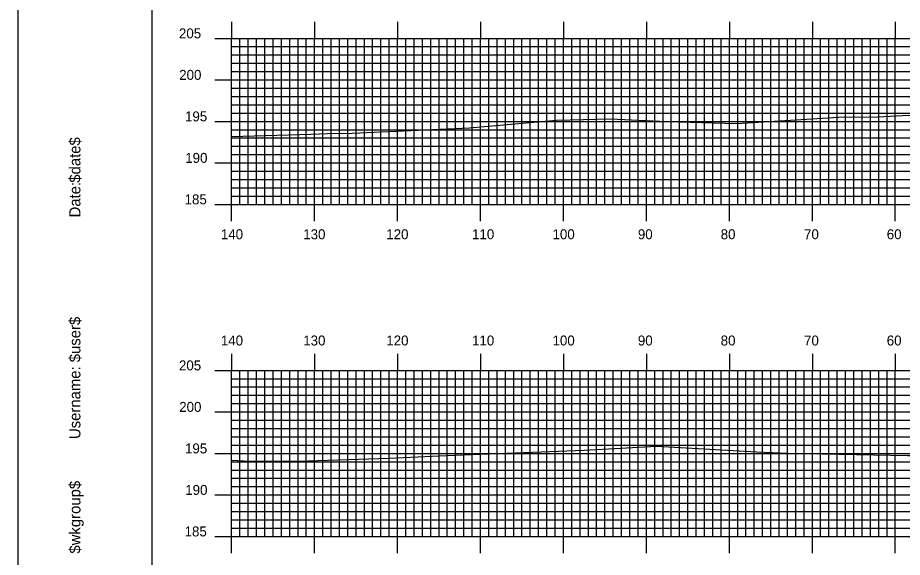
# Model space of a CAD drawing. Extents: x 1814522 to 1814865, y 442591 to 442811.
# Drawn here: x 1814521.7 to 1814628.4, y 442686.2 to 442751.2 of the extents above; entities that cross this region are included whole.
import ezdxf

# ---------------------------------------------------------------- set-up
doc = ezdxf.new("R2010")
doc.units = 0
for name, color, linetype in [('BORDER', 7, 'Continuous'), ('H_V ANNOTATION', 7, 'Continuous'), ('MAJOR', 7, 'Continuous'), ('MINOR', 7, 'Continuous'), ('PLOT BOUNDARY', 7, 'Continuous'), ('S_Roadway_Centerline', 7, 'Continuous')]:
    doc.layers.add(name, color=color, linetype=linetype)

msp = doc.modelspace()

# ---------------------------------------------------------------- linework, layer by layer
at = {"layer": 'BORDER'}
msp.add_lwpolyline([(1814537.91, 442596.67), (1814857.91, 442596.67), (1814857.91, 442806.67), (1814537.91, 442806.67)], close=True, dxfattribs=at)
at = {"layer": 'MAJOR'}
for p, q in [((1814547.51, 442750.67), (1814547.51, 442748.67)), ((1814557.51, 442750.67), (1814557.51, 442748.67)), ((1814567.51, 442750.67), (1814567.51, 442748.67)), ((1814577.51, 442750.67), (1814577.51, 442748.67)), ((1814587.51, 442750.67), (1814587.51, 442748.67)), ((1814597.51, 442750.67), (1814597.51, 442748.67)), ((1814607.51, 442750.67), (1814607.51, 442748.67)), ((1814617.51, 442750.67), (1814617.51, 442748.67)), ((1814627.51, 442750.67), (1814627.51, 442748.67)), ((1814545.5, 442748.67), (1814547.51, 442748.67)), ((1814547.51, 442748.67), (1814827.51, 442748.67)), ((1814547.51, 442728.67), (1814547.51, 442748.67)), ((1814547.51, 442728.67), (1814547.51, 442748.67)), ((1814547.51, 442748.67), (1814827.51, 442748.67)), ((1814557.51, 442728.67), (1814557.51, 442748.67)), ((1814567.51, 442728.67), (1814567.51, 442748.67)), ((1814577.51, 442728.67), (1814577.51, 442748.67)), ((1814587.51, 442728.67), (1814587.51, 442748.67)), ((1814597.51, 442728.67), (1814597.51, 442748.67)), ((1814607.51, 442728.67), (1814607.51, 442748.67)), ((1814617.51, 442728.67), (1814617.51, 442748.67)), ((1814627.51, 442728.67), (1814627.51, 442748.67)), ((1814545.5, 442743.67), (1814547.51, 442743.67)), ((1814547.51, 442743.67), (1814827.51, 442743.67)), ((1814545.5, 442738.67), (1814547.51, 442738.67)), ((1814547.51, 442738.67), (1814827.51, 442738.67)), ((1814545.5, 442733.67), (1814547.51, 442733.67)), ((1814547.51, 442733.67), (1814827.51, 442733.67)), ((1814545.5, 442728.67), (1814547.51, 442728.67)), ((1814547.51, 442728.67), (1814827.51, 442728.67)), ((1814547.51, 442728.67), (1814827.51, 442728.67)), ((1814547.51, 442726.66), (1814547.51, 442728.67)), ((1814557.51, 442726.66), (1814557.51, 442728.67)), ((1814567.51, 442726.66), (1814567.51, 442728.67)), ((1814577.51, 442726.66), (1814577.51, 442728.67)), ((1814587.51, 442726.66), (1814587.51, 442728.67)), ((1814597.51, 442726.66), (1814597.51, 442728.67)), ((1814607.51, 442726.66), (1814607.51, 442728.67)), ((1814617.51, 442726.66), (1814617.51, 442728.67)), ((1814627.51, 442726.66), (1814627.51, 442728.67)), ((1814547.51, 442710.67), (1814547.51, 442708.67)), ((1814557.51, 442710.67), (1814557.51, 442708.67)), ((1814567.51, 442710.67), (1814567.51, 442708.67)), ((1814577.51, 442710.67), (1814577.51, 442708.67)), ((1814587.51, 442710.67), (1814587.51, 442708.67)), ((1814597.51, 442710.67), (1814597.51, 442708.67)), ((1814607.51, 442710.67), (1814607.51, 442708.67)), ((1814617.51, 442710.67), (1814617.51, 442708.67)), ((1814627.51, 442710.67), (1814627.51, 442708.67)), ((1814545.5, 442708.67), (1814547.51, 442708.67)), ((1814547.51, 442708.67), (1814827.51, 442708.67)), ((1814547.51, 442688.67), (1814547.51, 442708.67)), ((1814547.51, 442688.67), (1814547.51, 442708.67)), ((1814547.51, 442708.67), (1814827.51, 442708.67)), ((1814557.51, 442688.67), (1814557.51, 442708.67)), ((1814567.51, 442688.67), (1814567.51, 442708.67)), ((1814577.51, 442688.67), (1814577.51, 442708.67)), ((1814587.51, 442688.67), (1814587.51, 442708.67)), ((1814597.51, 442688.67), (1814597.51, 442708.67)), ((1814607.51, 442688.67), (1814607.51, 442708.67)), ((1814617.51, 442688.67), (1814617.51, 442708.67)), ((1814627.51, 442688.67), (1814627.51, 442708.67)), ((1814545.5, 442703.67), (1814547.51, 442703.67)), ((1814547.51, 442703.67), (1814827.51, 442703.67)), ((1814545.5, 442698.67), (1814547.51, 442698.67)), ((1814547.51, 442698.67), (1814827.51, 442698.67)), ((1814545.5, 442693.67), (1814547.51, 442693.67)), ((1814547.51, 442693.67), (1814827.51, 442693.67)), ((1814545.5, 442688.67), (1814547.51, 442688.67)), ((1814547.51, 442688.67), (1814827.51, 442688.67)), ((1814547.51, 442688.67), (1814827.51, 442688.67)), ((1814547.51, 442686.66), (1814547.51, 442688.67)), ((1814557.51, 442686.66), (1814557.51, 442688.67)), ((1814567.51, 442686.66), (1814567.51, 442688.67)), ((1814577.51, 442686.66), (1814577.51, 442688.67)), ((1814587.51, 442686.66), (1814587.51, 442688.67)), ((1814597.51, 442686.66), (1814597.51, 442688.67)), ((1814607.51, 442686.66), (1814607.51, 442688.67)), ((1814617.51, 442686.66), (1814617.51, 442688.67)), ((1814627.51, 442686.66), (1814627.51, 442688.67))]:
    msp.add_line(p, q, dxfattribs=at)
at = {"layer": 'MINOR'}
for p, q in [((1814548.51, 442728.67), (1814548.51, 442748.67)), ((1814549.51, 442728.67), (1814549.51, 442748.67)), ((1814550.51, 442728.67), (1814550.51, 442748.67)), ((1814551.51, 442728.67), (1814551.51, 442748.67)), ((1814552.51, 442728.67), (1814552.51, 442748.67)), ((1814553.51, 442728.67), (1814553.51, 442748.67)), ((1814554.51, 442728.67), (1814554.51, 442748.67)), ((1814555.51, 442728.67), (1814555.51, 442748.67)), ((1814556.51, 442728.67), (1814556.51, 442748.67)), ((1814558.51, 442728.67), (1814558.51, 442748.67)), ((1814559.51, 442728.67), (1814559.51, 442748.67)), ((1814560.51, 442728.67), (1814560.51, 442748.67)), ((1814561.51, 442728.67), (1814561.51, 442748.67)), ((1814562.51, 442728.67), (1814562.51, 442748.67)), ((1814563.51, 442728.67), (1814563.51, 442748.67)), ((1814564.51, 442728.67), (1814564.51, 442748.67)), ((1814565.51, 442728.67), (1814565.51, 442748.67)), ((1814566.51, 442728.67), (1814566.51, 442748.67)), ((1814568.51, 442728.67), (1814568.51, 442748.67)), ((1814569.51, 442728.67), (1814569.51, 442748.67)), ((1814570.51, 442728.67), (1814570.51, 442748.67)), ((1814571.51, 442728.67), (1814571.51, 442748.67)), ((1814572.51, 442728.67), (1814572.51, 442748.67)), ((1814573.51, 442728.67), (1814573.51, 442748.67)), ((1814574.51, 442728.67), (1814574.51, 442748.67)), ((1814575.51, 442728.67), (1814575.51, 442748.67)), ((1814576.51, 442728.67), (1814576.51, 442748.67)), ((1814578.51, 442728.67), (1814578.51, 442748.67)), ((1814579.51, 442728.67), (1814579.51, 442748.67)), ((1814580.51, 442728.67), (1814580.51, 442748.67)), ((1814581.51, 442728.67), (1814581.51, 442748.67)), ((1814582.51, 442728.67), (1814582.51, 442748.67)), ((1814583.51, 442728.67), (1814583.51, 442748.67)), ((1814584.51, 442728.67), (1814584.51, 442748.67)), ((1814585.51, 442728.67), (1814585.51, 442748.67)), ((1814586.51, 442728.67), (1814586.51, 442748.67)), ((1814588.51, 442728.67), (1814588.51, 442748.67)), ((1814589.51, 442728.67), (1814589.51, 442748.67)), ((1814590.51, 442728.67), (1814590.51, 442748.67)), ((1814591.51, 442728.67), (1814591.51, 442748.67)), ((1814592.51, 442728.67), (1814592.51, 442748.67)), ((1814593.51, 442728.67), (1814593.51, 442748.67)), ((1814594.51, 442728.67), (1814594.51, 442748.67)), ((1814595.51, 442728.67), (1814595.51, 442748.67)), ((1814596.51, 442728.67), (1814596.51, 442748.67)), ((1814598.51, 442728.67), (1814598.51, 442748.67)), ((1814599.51, 442728.67), (1814599.51, 442748.67)), ((1814600.51, 442728.67), (1814600.51, 442748.67)), ((1814601.51, 442728.67), (1814601.51, 442748.67)), ((1814602.51, 442728.67), (1814602.51, 442748.67)), ((1814603.51, 442728.67), (1814603.51, 442748.67)), ((1814604.51, 442728.67), (1814604.51, 442748.67)), ((1814605.51, 442728.67), (1814605.51, 442748.67)), ((1814606.51, 442728.67), (1814606.51, 442748.67)), ((1814608.51, 442728.67), (1814608.51, 442748.67)), ((1814609.51, 442728.67), (1814609.51, 442748.67)), ((1814610.51, 442728.67), (1814610.51, 442748.67)), ((1814611.51, 442728.67), (1814611.51, 442748.67)), ((1814612.51, 442728.67), (1814612.51, 442748.67)), ((1814613.51, 442728.67), (1814613.51, 442748.67)), ((1814614.51, 442728.67), (1814614.51, 442748.67)), ((1814615.51, 442728.67), (1814615.51, 442748.67)), ((1814616.51, 442728.67), (1814616.51, 442748.67)), ((1814618.51, 442728.67), (1814618.51, 442748.67)), ((1814619.51, 442728.67), (1814619.51, 442748.67)), ((1814620.51, 442728.67), (1814620.51, 442748.67)), ((1814621.51, 442728.67), (1814621.51, 442748.67)), ((1814622.51, 442728.67), (1814622.51, 442748.67)), ((1814623.51, 442728.67), (1814623.51, 442748.67)), ((1814624.51, 442728.67), (1814624.51, 442748.67)), ((1814625.51, 442728.67), (1814625.51, 442748.67)), ((1814626.51, 442728.67), (1814626.51, 442748.67)), ((1814547.51, 442747.67), (1814827.51, 442747.67)), ((1814547.51, 442747.67), (1814549.51, 442747.67)), ((1814547.51, 442746.67), (1814827.51, 442746.67)), ((1814547.51, 442746.67), (1814549.51, 442746.67)), ((1814547.51, 442745.67), (1814827.51, 442745.67)), ((1814547.51, 442745.67), (1814549.51, 442745.67)), ((1814547.51, 442744.67), (1814827.51, 442744.67)), ((1814547.51, 442744.67), (1814549.51, 442744.67)), ((1814547.51, 442742.67), (1814827.51, 442742.67)), ((1814547.51, 442742.67), (1814549.51, 442742.67)), ((1814547.51, 442741.67), (1814827.51, 442741.67)), ((1814547.51, 442741.67), (1814549.51, 442741.67)), ((1814547.51, 442740.67), (1814827.51, 442740.67)), ((1814547.51, 442740.67), (1814549.51, 442740.67)), ((1814547.51, 442739.67), (1814827.51, 442739.67)), ((1814547.51, 442739.67), (1814549.51, 442739.67)), ((1814547.51, 442737.67), (1814827.51, 442737.67)), ((1814547.51, 442737.67), (1814549.51, 442737.67)), ((1814547.51, 442736.67), (1814827.51, 442736.67)), ((1814547.51, 442736.67), (1814549.51, 442736.67)), ((1814547.51, 442735.67), (1814827.51, 442735.67)), ((1814547.51, 442735.67), (1814549.51, 442735.67)), ((1814547.51, 442734.67), (1814827.51, 442734.67)), ((1814547.51, 442734.67), (1814549.51, 442734.67)), ((1814547.51, 442732.67), (1814827.51, 442732.67)), ((1814547.51, 442732.67), (1814549.51, 442732.67)), ((1814547.51, 442731.67), (1814827.51, 442731.67)), ((1814547.51, 442731.67), (1814549.51, 442731.67)), ((1814547.51, 442730.67), (1814827.51, 442730.67)), ((1814547.51, 442730.67), (1814549.51, 442730.67)), ((1814547.51, 442729.67), (1814827.51, 442729.67)), ((1814547.51, 442729.67), (1814549.51, 442729.67)), ((1814548.51, 442688.67), (1814548.51, 442708.67)), ((1814549.51, 442688.67), (1814549.51, 442708.67)), ((1814550.51, 442688.67), (1814550.51, 442708.67)), ((1814551.51, 442688.67), (1814551.51, 442708.67)), ((1814552.51, 442688.67), (1814552.51, 442708.67)), ((1814553.51, 442688.67), (1814553.51, 442708.67)), ((1814554.51, 442688.67), (1814554.51, 442708.67)), ((1814555.51, 442688.67), (1814555.51, 442708.67)), ((1814556.51, 442688.67), (1814556.51, 442708.67)), ((1814558.51, 442688.67), (1814558.51, 442708.67)), ((1814559.51, 442688.67), (1814559.51, 442708.67)), ((1814560.51, 442688.67), (1814560.51, 442708.67)), ((1814561.51, 442688.67), (1814561.51, 442708.67)), ((1814562.51, 442688.67), (1814562.51, 442708.67)), ((1814563.51, 442688.67), (1814563.51, 442708.67)), ((1814564.51, 442688.67), (1814564.51, 442708.67)), ((1814565.51, 442688.67), (1814565.51, 442708.67)), ((1814566.51, 442688.67), (1814566.51, 442708.67)), ((1814568.51, 442688.67), (1814568.51, 442708.67)), ((1814569.51, 442688.67), (1814569.51, 442708.67)), ((1814570.51, 442688.67), (1814570.51, 442708.67)), ((1814571.51, 442688.67), (1814571.51, 442708.67)), ((1814572.51, 442688.67), (1814572.51, 442708.67)), ((1814573.51, 442688.67), (1814573.51, 442708.67)), ((1814574.51, 442688.67), (1814574.51, 442708.67)), ((1814575.51, 442688.67), (1814575.51, 442708.67)), ((1814576.51, 442688.67), (1814576.51, 442708.67)), ((1814578.51, 442688.67), (1814578.51, 442708.67)), ((1814579.51, 442688.67), (1814579.51, 442708.67)), ((1814580.51, 442688.67), (1814580.51, 442708.67)), ((1814581.51, 442688.67), (1814581.51, 442708.67)), ((1814582.51, 442688.67), (1814582.51, 442708.67)), ((1814583.51, 442688.67), (1814583.51, 442708.67)), ((1814584.51, 442688.67), (1814584.51, 442708.67)), ((1814585.51, 442688.67), (1814585.51, 442708.67)), ((1814586.51, 442688.67), (1814586.51, 442708.67)), ((1814588.51, 442688.67), (1814588.51, 442708.67)), ((1814589.51, 442688.67), (1814589.51, 442708.67)), ((1814590.51, 442688.67), (1814590.51, 442708.67)), ((1814591.51, 442688.67), (1814591.51, 442708.67)), ((1814592.51, 442688.67), (1814592.51, 442708.67)), ((1814593.51, 442688.67), (1814593.51, 442708.67)), ((1814594.51, 442688.67), (1814594.51, 442708.67)), ((1814595.51, 442688.67), (1814595.51, 442708.67)), ((1814596.51, 442688.67), (1814596.51, 442708.67)), ((1814598.51, 442688.67), (1814598.51, 442708.67)), ((1814599.51, 442688.67), (1814599.51, 442708.67)), ((1814600.51, 442688.67), (1814600.51, 442708.67)), ((1814601.51, 442688.67), (1814601.51, 442708.67)), ((1814602.51, 442688.67), (1814602.51, 442708.67)), ((1814603.51, 442688.67), (1814603.51, 442708.67)), ((1814604.51, 442688.67), (1814604.51, 442708.67)), ((1814605.51, 442688.67), (1814605.51, 442708.67)), ((1814606.51, 442688.67), (1814606.51, 442708.67)), ((1814608.51, 442688.67), (1814608.51, 442708.67)), ((1814609.51, 442688.67), (1814609.51, 442708.67)), ((1814610.51, 442688.67), (1814610.51, 442708.67)), ((1814611.51, 442688.67), (1814611.51, 442708.67)), ((1814612.51, 442688.67), (1814612.51, 442708.67)), ((1814613.51, 442688.67), (1814613.51, 442708.67)), ((1814614.51, 442688.67), (1814614.51, 442708.67)), ((1814615.51, 442688.67), (1814615.51, 442708.67)), ((1814616.51, 442688.67), (1814616.51, 442708.67)), ((1814618.51, 442688.67), (1814618.51, 442708.67)), ((1814619.51, 442688.67), (1814619.51, 442708.67)), ((1814620.51, 442688.67), (1814620.51, 442708.67)), ((1814621.51, 442688.67), (1814621.51, 442708.67)), ((1814622.51, 442688.67), (1814622.51, 442708.67)), ((1814623.51, 442688.67), (1814623.51, 442708.67)), ((1814624.51, 442688.67), (1814624.51, 442708.67)), ((1814625.51, 442688.67), (1814625.51, 442708.67)), ((1814626.51, 442688.67), (1814626.51, 442708.67)), ((1814547.51, 442707.67), (1814827.51, 442707.67)), ((1814547.51, 442707.67), (1814549.51, 442707.67)), ((1814547.51, 442706.67), (1814827.51, 442706.67)), ((1814547.51, 442706.67), (1814549.51, 442706.67)), ((1814547.51, 442705.67), (1814827.51, 442705.67)), ((1814547.51, 442705.67), (1814549.51, 442705.67)), ((1814547.51, 442704.67), (1814827.51, 442704.67)), ((1814547.51, 442704.67), (1814549.51, 442704.67)), ((1814547.51, 442702.67), (1814827.51, 442702.67)), ((1814547.51, 442702.67), (1814549.51, 442702.67)), ((1814547.51, 442701.67), (1814827.51, 442701.67)), ((1814547.51, 442701.67), (1814549.51, 442701.67)), ((1814547.51, 442700.67), (1814827.51, 442700.67)), ((1814547.51, 442700.67), (1814549.51, 442700.67)), ((1814547.51, 442699.67), (1814827.51, 442699.67)), ((1814547.51, 442699.67), (1814549.51, 442699.67)), ((1814547.51, 442697.67), (1814827.51, 442697.67)), ((1814547.51, 442697.67), (1814549.51, 442697.67)), ((1814547.51, 442696.67), (1814827.51, 442696.67)), ((1814547.51, 442696.67), (1814549.51, 442696.67)), ((1814547.51, 442695.67), (1814827.51, 442695.67)), ((1814547.51, 442695.67), (1814549.51, 442695.67)), ((1814547.51, 442694.67), (1814827.51, 442694.67)), ((1814547.51, 442694.67), (1814549.51, 442694.67)), ((1814547.51, 442692.67), (1814827.51, 442692.67)), ((1814547.51, 442692.67), (1814549.51, 442692.67)), ((1814547.51, 442691.67), (1814827.51, 442691.67)), ((1814547.51, 442691.67), (1814549.51, 442691.67)), ((1814547.51, 442690.67), (1814827.51, 442690.67)), ((1814547.51, 442690.67), (1814549.51, 442690.67)), ((1814547.51, 442689.67), (1814827.51, 442689.67)), ((1814547.51, 442689.67), (1814549.51, 442689.67))]:
    msp.add_line(p, q, dxfattribs=at)
at = {"layer": 'PLOT BOUNDARY'}
msp.add_lwpolyline([(1814521.72, 442590.55), (1814861.72, 442590.55), (1814861.72, 442810.55), (1814521.72, 442810.55)], close=True, dxfattribs=at)
at = {"layer": 'S_Roadway_Centerline'}
for points in [[(1814547.51, 442736.83), (1814557.04, 442737.11), (1814559.08, 442737.2), (1814562.03, 442737.26), (1814576.2, 442737.9), (1814586.68, 442738.8), (1814593.17, 442738.96), (1814599.98, 442738.66), (1814608.42, 442738.43), (1814620.66, 442739.17), (1814625.4, 442739.21), (1814629.1, 442739.43), (1814642.75, 442738.97), (1814656.58, 442739.53), (1814658.13, 442739.6), (1814658.32, 442739.59), (1814684.97, 442739.55), (1814692.01, 442739.67), (1814696.95, 442739.75), (1814709.16, 442739.8), (1814718.81, 442739.81), (1814725.62, 442739.67), (1814732.24, 442738.99), (1814742.09, 442738.73)], [(1814547.51, 442697.84), (1814549.78, 442697.72), (1814555.44, 442697.74), (1814566.51, 442698.09), (1814573.41, 442698.43), (1814590, 442699.04), (1814598.78, 442699.54), (1814610.82, 442698.85), (1814614.58, 442698.7), (1814629, 442698.4), (1814631.14, 442698.4), (1814644.07, 442698.88), (1814647.19, 442699.01), (1814663.18, 442698.78), (1814663.37, 442698.77), (1814680.3, 442698.4), (1814684.53, 442698.65), (1814698.31, 442699.28), (1814709.41, 442699.33), (1814714.7, 442698.85), (1814721.94, 442699.2), (1814730.18, 442699.25), (1814739.58, 442699.13)]]:
    msp.add_lwpolyline(points, dxfattribs=at)

# ---------------------------------------------------------------- texts
at = {"layer": 'BORDER'}
for s, p in [('$date$', (1814529.28, 442731.28)), ('Date:', (1814529.28, 442727.1)), ('$user$', (1814529.28, 442709.65)), ('Username:', (1814529.28, 442700.4)), ('$wkgroup$', (1814529.28, 442686.6))]:
    msp.add_text(s, height=1.339, rotation=90, dxfattribs=at).set_placement(p)
at = {"layer": 'H_V ANNOTATION'}
for s, p in [('205', (1814541.16, 442748.67)), ('200', (1814541.19, 442743.67)), ('195', (1814541.89, 442738.67)), ('190', (1814541.92, 442733.67)), ('185', (1814541.84, 442728.67)), ('140', (1814546.21, 442724.47)), ('130', (1814556.14, 442724.47)), ('120', (1814566.15, 442724.47)), ('110', (1814576.49, 442724.47)), ('100', (1814586.19, 442724.47)), ('90', (1814596.48, 442724.47)), ('80', (1814606.46, 442724.47)), ('70', (1814616.51, 442724.47)), ('60', (1814626.48, 442724.47)), ('140', (1814546.21, 442711.67)), ('130', (1814556.14, 442711.67)), ('120', (1814566.15, 442711.67)), ('110', (1814576.49, 442711.67)), ('100', (1814586.19, 442711.67)), ('90', (1814596.48, 442711.67)), ('80', (1814606.46, 442711.67)), ('70', (1814616.51, 442711.67)), ('60', (1814626.48, 442711.67)), ('205', (1814541.16, 442708.67)), ('200', (1814541.19, 442703.67)), ('195', (1814541.89, 442698.67)), ('190', (1814541.92, 442693.67)), ('185', (1814541.84, 442688.67))]:
    msp.add_text(s, height=1.2, dxfattribs=at).set_placement(p)
at = {"layer": 'MAJOR'}
for p in [(1814547.5, 442728.67), (1814547.5, 442688.67)]:
    msp.add_text('-', height=0.012, dxfattribs=at).set_placement(p)

doc.saveas('drawing.dxf')
